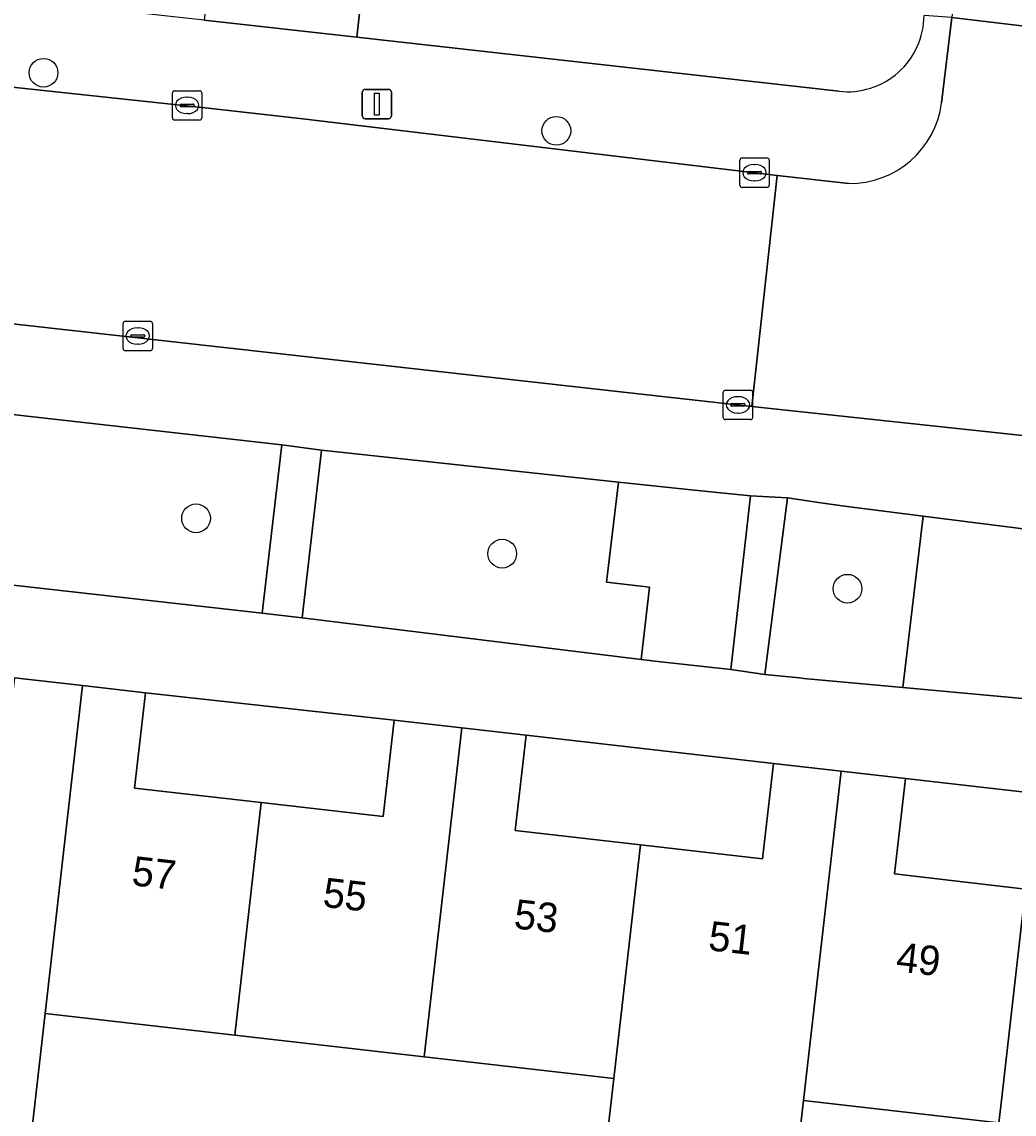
# Model space of a CAD drawing. Extents: x 161928 to 163071, y 386474 to 387428.
# Drawn here: x 162339.35 to 162373.15, y 386936.75 to 386973.94 of the extents above; entities that cross this region are included whole.
import ezdxf

# ---------------------------------------------------------------- set-up
doc = ezdxf.new("R2010")
doc.units = 0
for name, color, linetype in [('IMGEO_Boom', 7, 'Continuous'), ('IMGEO_Erf', 7, 'Continuous'), ('IMGEO_Groenvoorziening', 7, 'Continuous'), ('IMGEO_Kolk', 7, 'Continuous'), ('IMGEO_Lichtmast', 7, 'Continuous'), ('IMGEO_Pand', 7, 'Continuous'), ('IMGEO_Pand_nummerreeks', 7, 'Continuous'), ('IMGEO_Rijbaan_lokaal_gesloten', 7, 'Continuous'), ('IMGEO_Rijbaan_lokaal_open', 7, 'Continuous'), ('IMGEO_Voetpad_open', 7, 'Continuous')]:
    doc.layers.add(name, color=color, linetype=linetype)

msp = doc.modelspace()

# ---------------------------------------------------------------- linework, layer by layer
at = {"layer": 'IMGEO_Boom'}
for centre in [(162340.086, 386972.205), (162357.553, 386970.228), (162345.281, 386957.036), (162355.708, 386955.832), (162367.469, 386954.64)]:
    msp.add_circle(centre, 0.489, dxfattribs=at)
at = {"layer": 'IMGEO_Erf'}
for points in [[(162359.152, 386934.802), (162359.513, 386937.961), (162353.055, 386938.7), (162346.598, 386939.438), (162340.14, 386940.177), (162339.684, 386936.19), (162333.226, 386936.928), (162333.682, 386940.915), (162327.224, 386941.654), (162320.57, 386942.415), (162321.47, 386950.28), (162325.781, 386949.787), (162326.154, 386953.042), (162319.707, 386953.719), (162317.449, 386953.956), (162315.158, 386933.583)], [(162375.891, 386947.445), (162369.443, 386948.18), (162369.071, 386944.928), (162373.537, 386944.417), (162372.691, 386937.023), (162372.627, 386936.461), (162365.971, 386937.222), (162365.61, 386934.063)]]:
    msp.add_lwpolyline(points, dxfattribs=at)
for points in [[(162343.561, 386951.1), (162343.189, 386947.853), (162347.504, 386947.36), (162351.659, 386946.885), (162352.034, 386950.165)], [(162356.526, 386949.651), (162356.155, 386946.407), (162360.423, 386945.919), (162364.572, 386945.444), (162364.944, 386948.694)]]:
    msp.add_lwpolyline(points, close=True, dxfattribs=at)
at = {"layer": 'IMGEO_Groenvoorziening'}
for points in [[(162358.078, 386975.691), (162351.103, 386976.499), (162350.757, 386973.412), (162367.17, 386971.574)], [(162376.411, 386956.299), (162370.042, 386957.109), (162369.353, 386951.278), (162375.782, 386950.69)]]:
    msp.add_lwpolyline(points, dxfattribs=at)
for points in [[(162348.204, 386959.539), (162338.107, 386960.674), (162337.225, 386954.968), (162347.536, 386953.806)], [(162359.67, 386958.272), (162349.555, 386959.361), (162348.897, 386953.648), (162360.442, 386952.229), (162360.72, 386954.687), (162359.263, 386954.86)], [(162364.163, 386957.8), (162362.146, 386958.005), (162359.67, 386958.272), (162359.263, 386954.86), (162360.72, 386954.687), (162360.442, 386952.229), (162361.014, 386952.159), (162363.496, 386951.885)], [(162370.042, 386957.109), (162367.368, 386957.449), (162366.556, 386957.568), (162365.423, 386957.734), (162364.65, 386951.716), (162365.833, 386951.601), (162365.982, 386951.587), (162369.353, 386951.278)]]:
    msp.add_lwpolyline(points, close=True, dxfattribs=at)
msp.add_arc((162367.462, 386974.171), 2.614, 263.5786, 359.686, dxfattribs=at)
at = {"layer": 'IMGEO_Kolk'}
for p, q in [((162344.476, 386970.667), (162344.476, 386971.519)), ((162344.551, 386971.593), (162345.403, 386971.593)), ((162344.964, 386971.373), (162344.989, 386971.373)), ((162345.477, 386971.519), (162345.477, 386970.667)), ((162344.735, 386971.087), (162344.735, 386971.099)), ((162345.173, 386971.05), (162344.775, 386971.05)), ((162344.778, 386971.136), (162345.176, 386971.136)), ((162345.219, 386971.099), (162345.219, 386971.087)), ((162344.987, 386970.813), (162344.962, 386970.813)), ((162345.403, 386970.593), (162344.551, 386970.593)), ((162363.802, 386968.377), (162363.802, 386969.229)), ((162363.877, 386969.303), (162364.729, 386969.303)), ((162364.803, 386969.229), (162364.803, 386968.377)), ((162364.061, 386968.797), (162364.061, 386968.809)), ((162364.499, 386968.76), (162364.101, 386968.76)), ((162364.104, 386968.846), (162364.502, 386968.846)), ((162364.29, 386969.083), (162364.315, 386969.083)), ((162364.545, 386968.809), (162364.545, 386968.797)), ((162364.313, 386968.523), (162364.288, 386968.523)), ((162364.729, 386968.303), (162363.877, 386968.303)), ((162342.795, 386962.817), (162342.795, 386963.669)), ((162342.87, 386963.743), (162343.722, 386963.743)), ((162343.796, 386963.669), (162343.796, 386962.817)), ((162343.054, 386963.237), (162343.054, 386963.249)), ((162343.492, 386963.2), (162343.094, 386963.2)), ((162343.097, 386963.286), (162343.495, 386963.286)), ((162343.283, 386963.523), (162343.308, 386963.523)), ((162343.538, 386963.249), (162343.538, 386963.237)), ((162343.306, 386962.963), (162343.281, 386962.963)), ((162343.722, 386962.743), (162342.87, 386962.743)), ((162363.238, 386960.472), (162363.238, 386961.324)), ((162363.313, 386961.398), (162364.165, 386961.398)), ((162364.239, 386961.324), (162364.239, 386960.472)), ((162363.726, 386961.178), (162363.751, 386961.178)), ((162363.497, 386960.892), (162363.497, 386960.904)), ((162363.935, 386960.855), (162363.537, 386960.855)), ((162363.54, 386960.941), (162363.938, 386960.941)), ((162363.749, 386960.618), (162363.724, 386960.618)), ((162363.981, 386960.904), (162363.981, 386960.892)), ((162364.165, 386960.398), (162363.313, 386960.398))]:
    msp.add_line(p, q, dxfattribs=at)
for points in [[(162344.476, 386970.667), (162344.476, 386971.519)], [(162344.551, 386971.593), (162345.403, 386971.593)], [(162345.477, 386971.519), (162345.477, 386970.667)], [(162345.403, 386970.593), (162344.551, 386970.593)], [(162363.802, 386968.377), (162363.802, 386969.229)], [(162363.877, 386969.303), (162364.729, 386969.303)], [(162364.803, 386969.229), (162364.803, 386968.377)], [(162364.729, 386968.303), (162363.877, 386968.303)], [(162342.795, 386962.817), (162342.795, 386963.669)], [(162342.87, 386963.743), (162343.722, 386963.743)], [(162343.796, 386963.669), (162343.796, 386962.817)], [(162343.722, 386962.743), (162342.87, 386962.743)], [(162363.238, 386960.472), (162363.238, 386961.324)], [(162363.313, 386961.398), (162364.165, 386961.398)], [(162364.239, 386961.324), (162364.239, 386960.472)], [(162364.165, 386960.398), (162363.313, 386960.398)]]:
    msp.add_lwpolyline(points, dxfattribs=at)
for centre, radius, start, end in [((162344.553, 386971.517), 0.0765, 91.552, 178.448), ((162344.553, 386971.517), 0.0765, 91.552, 178.448), ((162345.401, 386971.517), 0.0765, 1.552, 88.448), ((162345.401, 386971.517), 0.0765, 1.552, 88.448), ((162344.775, 386971.096), 0.0403, 85.8775, 175.7526), ((162344.772, 386971.086), 0.0366, 178.938, 274.7102), ((162345.176, 386971.093), 0.043, 264.8664, 352.4533), ((162345.18, 386971.098), 0.0386, 1.7309, 96.639), ((162344.553, 386970.669), 0.0765, 181.552, 268.448), ((162344.553, 386970.669), 0.0765, 181.552, 268.448), ((162345.401, 386970.669), 0.0765, 271.552, 358.448), ((162345.401, 386970.669), 0.0765, 271.552, 358.448), ((162363.879, 386969.227), 0.0765, 91.552, 178.448), ((162363.879, 386969.227), 0.0765, 91.552, 178.448), ((162364.727, 386969.227), 0.0765, 1.552, 88.448), ((162364.727, 386969.227), 0.0765, 1.552, 88.448), ((162364.101, 386968.806), 0.0403, 85.8775, 175.7526), ((162364.098, 386968.796), 0.0366, 178.938, 274.7102), ((162364.502, 386968.803), 0.043, 264.8664, 352.4533), ((162364.506, 386968.808), 0.0386, 1.7309, 96.639), ((162363.879, 386968.379), 0.0765, 181.552, 268.448), ((162363.879, 386968.379), 0.0765, 181.552, 268.448), ((162364.727, 386968.379), 0.0765, 271.552, 358.448), ((162364.727, 386968.379), 0.0765, 271.552, 358.448), ((162342.872, 386963.667), 0.0765, 91.552, 178.448), ((162342.872, 386963.667), 0.0765, 91.552, 178.448), ((162343.72, 386963.667), 0.0765, 1.552, 88.448), ((162343.72, 386963.667), 0.0765, 1.552, 88.448), ((162343.094, 386963.246), 0.0403, 85.8775, 175.7526), ((162343.091, 386963.236), 0.0366, 178.938, 274.7102), ((162343.495, 386963.243), 0.043, 264.8664, 352.4533), ((162343.499, 386963.248), 0.0386, 1.7309, 96.639), ((162342.872, 386962.819), 0.0765, 181.552, 268.448), ((162342.872, 386962.819), 0.0765, 181.552, 268.448), ((162343.72, 386962.819), 0.0765, 271.552, 358.448), ((162343.72, 386962.819), 0.0765, 271.552, 358.448), ((162363.315, 386961.322), 0.0765, 91.552, 178.448), ((162363.315, 386961.322), 0.0765, 91.552, 178.448), ((162364.163, 386961.322), 0.0765, 1.552, 88.448), ((162364.163, 386961.322), 0.0765, 1.552, 88.448), ((162363.537, 386960.901), 0.0403, 85.8775, 175.7526), ((162363.534, 386960.891), 0.0366, 178.938, 274.7102), ((162363.938, 386960.898), 0.043, 264.8664, 352.4533), ((162363.942, 386960.903), 0.0386, 1.7309, 96.639), ((162363.315, 386960.474), 0.0765, 181.552, 268.448), ((162363.315, 386960.474), 0.0765, 181.552, 268.448), ((162364.163, 386960.474), 0.0765, 271.552, 358.448), ((162364.163, 386960.474), 0.0765, 271.552, 358.448)]:
    msp.add_arc(centre, radius, start, end, dxfattribs=at)
for centre, major_axis, ratio, start_param, end_param in [((162344.963, 386971.093), (-0.387, 0.002), 0.722429, 4.712389, 7.853982), ((162344.988, 386971.093), (-0.39, 0.002), 0.717154, 1.570796, 4.712389), ((162364.289, 386968.803), (-0.387, 0.002), 0.722429, 4.712389, 7.853982), ((162364.314, 386968.803), (-0.39, 0.002), 0.717154, 1.570796, 4.712389), ((162343.282, 386963.243), (-0.387, 0.002), 0.722429, 4.712389, 7.853982), ((162343.307, 386963.243), (-0.39, 0.002), 0.717154, 1.570796, 4.712389), ((162363.725, 386960.898), (-0.387, 0.002), 0.722429, 4.712389, 7.853982), ((162363.75, 386960.898), (-0.39, 0.002), 0.717154, 1.570796, 4.712389)]:
    msp.add_ellipse(centre, major_axis=major_axis, ratio=ratio, start_param=start_param, end_param=end_param, dxfattribs=at)
at = {"layer": 'IMGEO_Lichtmast'}
for p, q in [((162350.943, 386970.739), (162350.943, 386971.539)), ((162350.943, 386971.539), (162350.943, 386970.739)), ((162351.043, 386971.639), (162351.833, 386971.639)), ((162351.833, 386971.639), (162351.043, 386971.639)), ((162351.933, 386971.539), (162351.933, 386970.739)), ((162351.933, 386970.739), (162351.933, 386971.539)), ((162351.833, 386970.639), (162351.043, 386970.639)), ((162351.043, 386970.639), (162351.833, 386970.639))]:
    msp.add_line(p, q, dxfattribs=at)
msp.add_lwpolyline([(162351.363, 386971.514), (162351.513, 386971.514), (162351.513, 386970.764), (162351.363, 386970.764), (162351.363, 386971.514)], dxfattribs=at)
for centre, start, end in [((162351.043, 386971.539), 90, 180), ((162351.043, 386971.539), 90, 180), ((162351.833, 386971.539), 0, 90), ((162351.833, 386971.539), 360, 90), ((162351.043, 386970.739), 180, 270), ((162351.043, 386970.739), 180, 270), ((162351.833, 386970.739), 270, 0), ((162351.833, 386970.739), 270, 0)]:
    msp.add_arc(centre, 0.1, start, end, dxfattribs=at)
at = {"layer": 'IMGEO_Pand'}
for points in [[(162341.417, 386951.345), (162339.098, 386951.611), (162338.724, 386948.337), (162334.585, 386948.811), (162333.682, 386940.915), (162333.226, 386936.928), (162339.684, 386936.19), (162340.14, 386940.177)], [(162341.417, 386951.345), (162340.14, 386940.177), (162346.598, 386939.438), (162347.504, 386947.36), (162343.189, 386947.853), (162343.561, 386951.1)], [(162352.034, 386950.165), (162351.659, 386946.885), (162347.504, 386947.36), (162346.598, 386939.438), (162353.055, 386938.7), (162354.336, 386949.902)], [(162354.336, 386949.902), (162353.055, 386938.7), (162359.513, 386937.961), (162360.423, 386945.919), (162356.155, 386946.407), (162356.526, 386949.651)], [(162367.253, 386948.43), (162364.944, 386948.694), (162364.572, 386945.444), (162360.423, 386945.919), (162359.513, 386937.961), (162359.152, 386934.802), (162365.61, 386934.063), (162365.971, 386937.222)], [(162367.253, 386948.43), (162365.971, 386937.222), (162372.627, 386936.461), (162372.691, 386937.023), (162373.537, 386944.417), (162369.071, 386944.928), (162369.443, 386948.18)]]:
    msp.add_lwpolyline(points, close=True, dxfattribs=at)
at = {"layer": 'IMGEO_Rijbaan_lokaal_gesloten'}
msp.add_lwpolyline([(162322.801, 386965.472), (162327.146, 386964.983), (162361.867, 386961.107), (162364.207, 386960.846), (162365.074, 386968.71), (162362.412, 386969.03), (162348.916, 386970.641), (162345.485, 386971.026), (162328.736, 386972.812), (162323.738, 386973.385)], close=True, dxfattribs=at)
at = {"layer": 'IMGEO_Rijbaan_lokaal_open'}
for points in [[(162378.678, 387041.833), (162374.021, 387000), (162371.186, 386975.48), (162371.02, 386974.085), (162375.974, 386973.494), (162376.384, 386977.172), (162378.727, 386996.574), (162379.106, 387000), (162382.527, 387030.958), (162383.804, 387042.513), (162380.226, 387042.899)], [(162375.619, 386970.31), (162375.678, 386970.841), (162375.974, 386973.494), (162371.02, 386974.085), (162370.675, 386971.181)], [(162367.512, 386968.436), (162365.074, 386968.71), (162364.207, 386960.846), (162373.963, 386959.795), (162376.975, 386959.351)]]:
    msp.add_lwpolyline(points, dxfattribs=at)
msp.add_arc((162367.549, 386971.588), 3.152, 269.3218, 352.5841, dxfattribs=at)
at = {"layer": 'IMGEO_Voetpad_open'}
for points in [[(162351.103, 386976.499), (162348.834, 386976.762), (162348.807, 386976.765), (162346.122, 386977.064), (162345.909, 386977.088), (162345.562, 386973.994), (162350.757, 386973.412)], [(162349.555, 386959.361), (162348.204, 386959.539), (162347.536, 386953.806), (162348.897, 386953.648)], [(162365.423, 386957.734), (162364.163, 386957.8), (162363.496, 386951.885), (162364.65, 386951.716)]]:
    msp.add_lwpolyline(points, close=True, dxfattribs=at)
for points in [[(162350.757, 386973.412), (162345.562, 386973.994), (162344.306, 386974.135), (162337.869, 386974.856), (162327.435, 386976.025), (162324.155, 386976.393), (162322.946, 386976.528), (162322.698, 386973.515), (162323.738, 386973.385), (162328.736, 386972.812), (162345.485, 386971.026), (162348.916, 386970.641), (162362.412, 386969.03), (162365.074, 386968.71), (162367.512, 386968.436)], [(162370.675, 386971.181), (162371.02, 386974.085), (162370.076, 386974.157)], [(162367.17, 386971.574), (162350.757, 386973.412)], [(162327.146, 386964.983), (162322.801, 386965.472), (162321.767, 386965.569), (162321.768, 386962.553), (162326.836, 386961.97), (162331.634, 386961.401), (162332.628, 386961.289), (162338.107, 386960.674), (162348.204, 386959.539), (162349.555, 386959.361), (162359.67, 386958.272), (162362.146, 386958.005), (162364.163, 386957.8), (162365.423, 386957.734), (162366.556, 386957.568), (162367.368, 386957.449), (162370.042, 386957.109), (162376.411, 386956.299)], [(162376.975, 386959.351), (162373.963, 386959.795), (162364.207, 386960.846), (162361.867, 386961.107), (162327.146, 386964.983)], [(162318.106, 386959.14), (162317.449, 386953.956), (162319.707, 386953.719), (162326.154, 386953.042), (162328.496, 386952.774), (162330.67, 386952.526), (162339.098, 386951.611), (162341.417, 386951.345), (162343.561, 386951.1), (162352.034, 386950.165), (162354.336, 386949.902), (162356.526, 386949.651), (162364.944, 386948.694), (162367.253, 386948.43), (162369.443, 386948.18), (162375.891, 386947.445)], [(162348.897, 386953.648), (162347.536, 386953.806), (162337.225, 386954.968), (162331.225, 386955.645), (162331.07, 386955.662), (162326.521, 386955.951), (162320.804, 386956.567)], [(162375.782, 386950.69), (162369.353, 386951.278), (162365.982, 386951.587), (162365.833, 386951.601), (162364.65, 386951.716), (162363.496, 386951.885), (162361.014, 386952.159), (162360.442, 386952.229), (162348.897, 386953.648)]]:
    msp.add_lwpolyline(points, dxfattribs=at)
for centre, radius, start, end in [((162367.462, 386974.171), 2.614, 263.5786, 359.686), ((162367.549, 386971.588), 3.152, 269.3218, 352.5841)]:
    msp.add_arc(centre, radius, start, end, dxfattribs=at)

# ---------------------------------------------------------------- texts
at = {"layer": 'IMGEO_Pand_nummerreeks'}
for s, rotation, p in [('57', 353.5753, (162343.061, 386944.548)), ('55', 353.5753, (162349.569, 386943.815)), ('53', 353.5753, (162356.078, 386943.082)), ('51', 353.5771, (162362.699, 386942.337)), ('49', 353.5753, (162369.094, 386941.617))]:
    msp.add_text(s, height=1, rotation=rotation, dxfattribs=at).set_placement(p)

doc.saveas('drawing.dxf')
